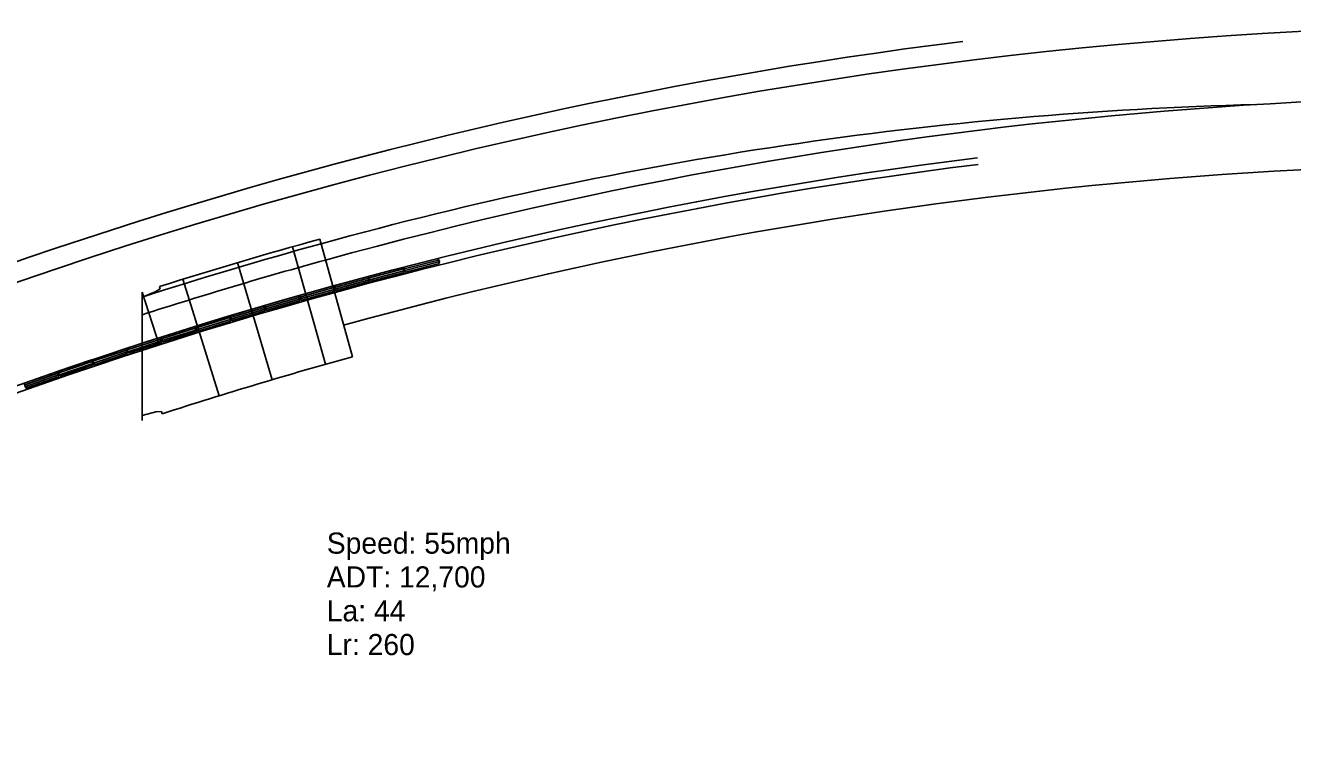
# Model space of a CAD drawing. Extents: x 24523748 to 24530451, y 6406056 to 6407486.
# Drawn here: x 24527439.4 to 24527888.9, y 6407220 to 6407473.2 of the extents above; entities that cross this region are included whole.
import ezdxf

# ---------------------------------------------------------------- set-up
doc = ezdxf.new("R2010")
doc.units = 0
for name, color, linetype in [('dsnCellElements', 7, 'Continuous'), ('dsnNonPlotable', 7, 'Continuous'), ('EdgePaved', 7, 'Continuous'), ('EdgeShoulder', 7, 'Continuous'), ('Joints', 7, 'Continuous'), ('Level 2', 7, 'Continuous')]:
    doc.layers.add(name, color=color, linetype=linetype)

msp = doc.modelspace()

# ---------------------------------------------------------------- linework, layer by layer
at = {"layer": 'dsnCellElements'}
msp.add_arc((24527910.59, 6406074.25), 1371.28, 91.45551, 105.49305, dxfattribs=at)
at = {"layer": 'dsnNonPlotable'}
for centre in [(24527573.74, 6407386.45), (24527573.74, 6407386.45), (24527586.15, 6407389.6), (24527561.36, 6407383.19), (24527561.36, 6407383.19), (24527549, 6407379.84), (24527549, 6407379.84), (24527524.38, 6407372.83), (24527524.38, 6407372.83), (24527536.68, 6407376.38), (24527536.68, 6407376.38), (24527512.11, 6407369.18), (24527512.11, 6407369.18), (24527499.86, 6407365.44), (24527499.86, 6407365.44), (24527487.65, 6407361.6), (24527487.65, 6407361.6), (24527475.47, 6407357.65), (24527475.47, 6407357.65), (24527463.32, 6407353.62), (24527463.32, 6407353.62), (24527451.21, 6407349.48), (24527451.21, 6407349.48)]:
    msp.add_circle(centre, 0.0521, dxfattribs=at)
for centre, radius, start, end in [((24527976.2, 6405830.59), 1649.63, 97.11247, 120.07637), ((24527976.2, 6405830.59), 1617.62, 62.73567, 105.42738), ((24527976.2, 6405830.59), 1608, 97.11247, 120.07637), ((24527976.2, 6405830.59), 1605.63, 97.11247, 120.07637), ((24527976.2, 6405830.59), 1593.62, 62.73567, 105.42738), ((24527573.59, 6407386.41), 0.281, 284.734, 104.734), ((24527573.89, 6407386.48), 0.281, 104.2666, 284.2666), ((24527586, 6407389.56), 0.281, 284.2666, 104.2666), ((24527561.21, 6407383.15), 0.281, 285.187, 105.187), ((24527561.51, 6407383.23), 0.281, 104.734, 284.734), ((24527536.53, 6407376.34), 0.281, 286.1098, 106.1098), ((24527536.82, 6407376.42), 0.281, 105.65, 285.65), ((24527548.86, 6407379.8), 0.281, 285.65, 105.65), ((24527549.15, 6407379.88), 0.281, 105.187, 285.187), ((24527524.23, 6407372.79), 0.281, 286.5559, 106.5559), ((24527524.52, 6407372.87), 0.281, 106.1098, 286.1098), ((24527511.96, 6407369.14), 0.281, 287.0205, 107.0205), ((24527512.25, 6407369.23), 0.281, 106.5559, 286.5559), ((24527499.72, 6407365.39), 0.281, 287.4531, 107.4531), ((24527500.01, 6407365.48), 0.281, 107.0205, 287.0205), ((24527487.51, 6407361.55), 0.281, 287.935, 107.935), ((24527487.8, 6407361.64), 0.281, 107.4531, 287.4531), ((24527475.33, 6407357.61), 0.281, 288.3874, 108.3874), ((24527475.62, 6407357.7), 0.281, 107.935, 287.935), ((24527451.06, 6407349.43), 0.281, 289.2888, 109.2888), ((24527451.35, 6407349.53), 0.281, 108.8459, 288.8459), ((24527463.18, 6407353.57), 0.281, 288.8459, 108.8459), ((24527463.47, 6407353.66), 0.281, 108.3874, 288.3874)]:
    msp.add_arc(centre, radius, start, end, dxfattribs=at)
at = {"layer": 'EdgePaved'}
for p, q in [((24527543.84, 6407397.35), (24527555.37, 6407355.57)), ((24527480.79, 6407378.54), (24527480.79, 6407332.98)), ((24527486.94, 6407380.53), (24527487.21, 6407379.67)), ((24527487.96, 6407335.34), (24527487.68, 6407336.19))]:
    msp.add_line(p, q, dxfattribs=at)
for points in [[(24527480.79, 6407376.79), (24527485.47, 6407378.58), (24527487.21, 6407379.67)], [(24527480.79, 6407334.73), (24527485.62, 6407336.04), (24527487.68, 6407336.19)]]:
    msp.add_lwpolyline(points, dxfattribs=at)
for radius, start, end in [(1642.62, 62.73567, 120.5348), (1625.32, 105.42738, 107.51898), (1581.98, 105.42738, 107.97645)]:
    msp.add_arc((24527976.2, 6405830.59), radius, start, end, dxfattribs=at)
at = {"layer": 'EdgeShoulder'}
for radius, end in [(1623.62, 107.76572), (1617.62, 107.83382)]:
    msp.add_arc((24527976.2, 6405830.59), radius, 105.42738, end, dxfattribs=at)
at = {"layer": 'Joints'}
for p, q in [((24527534.09, 6407394.63), (24527545.88, 6407352.92)), ((24527514.64, 6407389), (24527526.95, 6407347.44)), ((24527495.27, 6407383.13), (24527508.09, 6407341.72)), ((24527480.79, 6407378.54), (24527486.79, 6407359.81))]:
    msp.add_line(p, q, dxfattribs=at)
at = {"layer": 'Level 2'}
for p, q in [((24527573.66, 6407387.39), (24527585.77, 6407390.47)), ((24527586.23, 6407388.66), (24527585.77, 6407390.47)), ((24527561.27, 6407384.14), (24527573.36, 6407387.32)), ((24527561.42, 6407383.56), (24527573.51, 6407386.74)), ((24527561.59, 6407382.9), (24527573.68, 6407386.08)), ((24527561.74, 6407382.32), (24527573.83, 6407385.5)), ((24527573.83, 6407385.5), (24527573.36, 6407387.32)), ((24527574.12, 6407385.58), (24527573.66, 6407387.39)), ((24527573.8, 6407386.81), (24527585.92, 6407389.89)), ((24527573.97, 6407386.16), (24527586.08, 6407389.24)), ((24527574.12, 6407385.58), (24527586.23, 6407388.66)), ((24527548.9, 6407380.78), (24527560.97, 6407384.06)), ((24527549.06, 6407380.2), (24527561.12, 6407383.48)), ((24527549.24, 6407379.55), (24527561.3, 6407382.83)), ((24527549.4, 6407378.97), (24527561.46, 6407382.25)), ((24527561.46, 6407382.25), (24527560.97, 6407384.06)), ((24527561.74, 6407382.32), (24527561.27, 6407384.14)), ((24527524.26, 6407373.77), (24527536.27, 6407377.24)), ((24527524.43, 6407373.2), (24527536.44, 6407376.67)), ((24527536.79, 6407375.44), (24527536.27, 6407377.24)), ((24527536.57, 6407377.33), (24527548.61, 6407380.7)), ((24527537.07, 6407375.52), (24527536.57, 6407377.33)), ((24527536.73, 6407376.75), (24527548.77, 6407380.12)), ((24527536.91, 6407376.1), (24527548.95, 6407379.47)), ((24527537.07, 6407375.52), (24527549.11, 6407378.89)), ((24527549.11, 6407378.89), (24527548.61, 6407380.7)), ((24527549.4, 6407378.97), (24527548.9, 6407380.78)), ((24527511.98, 6407370.13), (24527523.97, 6407373.69)), ((24527512.15, 6407369.55), (24527524.14, 6407373.11)), ((24527512.35, 6407368.9), (24527524.33, 6407372.46)), ((24527524.5, 6407371.89), (24527523.97, 6407373.69)), ((24527524.78, 6407371.97), (24527524.26, 6407373.77)), ((24527524.62, 6407372.55), (24527536.62, 6407376.02)), ((24527524.78, 6407371.97), (24527536.79, 6407375.44)), ((24527499.73, 6407366.38), (24527511.69, 6407370.04)), ((24527499.91, 6407365.8), (24527511.86, 6407369.46)), ((24527500.11, 6407365.16), (24527512.06, 6407368.82)), ((24527500.28, 6407364.58), (24527512.24, 6407368.24)), ((24527512.24, 6407368.24), (24527511.69, 6407370.04)), ((24527512.52, 6407368.33), (24527511.98, 6407370.13)), ((24527512.52, 6407368.33), (24527524.5, 6407371.89)), ((24527487.51, 6407362.54), (24527499.44, 6407366.29)), ((24527487.69, 6407361.96), (24527499.62, 6407365.71)), ((24527487.9, 6407361.32), (24527499.82, 6407365.07)), ((24527488.08, 6407360.75), (24527500, 6407364.5)), ((24527500, 6407364.5), (24527499.44, 6407366.29)), ((24527500.28, 6407364.58), (24527499.73, 6407366.38)), ((24527475.33, 6407358.59), (24527487.22, 6407362.44)), ((24527475.9, 6407356.81), (24527475.33, 6407358.59)), ((24527475.51, 6407358.02), (24527487.4, 6407361.87)), ((24527475.72, 6407357.38), (24527487.61, 6407361.23)), ((24527475.9, 6407356.81), (24527487.8, 6407360.66)), ((24527487.8, 6407360.66), (24527487.22, 6407362.44)), ((24527488.08, 6407360.75), (24527487.51, 6407362.54)), ((24527451.05, 6407350.42), (24527462.88, 6407354.45)), ((24527463.48, 6407352.68), (24527462.88, 6407354.45)), ((24527463.17, 6407354.55), (24527475.03, 6407358.5)), ((24527463.76, 6407352.77), (24527463.17, 6407354.55)), ((24527463.36, 6407353.98), (24527475.22, 6407357.93)), ((24527463.57, 6407353.34), (24527475.43, 6407357.29)), ((24527463.76, 6407352.77), (24527475.62, 6407356.72)), ((24527475.62, 6407356.72), (24527475.03, 6407358.5)), ((24527438.96, 6407346.19), (24527450.75, 6407350.32)), ((24527439.15, 6407345.62), (24527450.95, 6407349.75)), ((24527451.37, 6407348.55), (24527450.75, 6407350.32)), ((24527451.65, 6407348.64), (24527451.05, 6407350.42)), ((24527451.24, 6407349.85), (24527463.07, 6407353.89)), ((24527451.46, 6407349.21), (24527463.29, 6407353.25)), ((24527451.65, 6407348.64), (24527463.48, 6407352.68)), ((24527439.58, 6407344.42), (24527438.96, 6407346.19)), ((24527439.38, 6407344.98), (24527451.18, 6407349.11)), ((24527439.58, 6407344.42), (24527451.37, 6407348.55))]:
    msp.add_line(p, q, dxfattribs=at)

# ---------------------------------------------------------------- texts
at = {"layer": 'dsnNonPlotable'}
for s, p in [('Speed: 55mph', (24527546.3, 6407285.69)), ('ADT: 12,700', (24527546.3, 6407273.69)), ('La: 44', (24527546.3, 6407261.69)), ('Lr: 260', (24527546.3, 6407249.69))]:
    msp.add_text(s, height=7.5, dxfattribs=at).set_placement(p)

doc.saveas('drawing.dxf')
